Omron CX-Programmer project NewProject (CX-Programmer 7.23)

# PLC NewPLC1: CP1L L

## Program NewProgram1 (cyclic task 0)
; This program measures the amount of material that goes past a sensor using an encoder. / When the sensor is on we count the pulses from the High Speed Counter. / The E6B2-CWZ6C Encoder has 1000 pulses per revolution. / Because it is differential (A,B&Z Phases) we actually get 4000 pulses per revolution. / 1 revolution of the encoder equates to 1 foot of material. / Therefore the length of material in inches = pulses * 12 / 4000.
Local symbols
Gate_HSC_0 A531.08 BOOL
HSC0_PV A270 DINT
HSC0_PV_Inches D110 DINT
HSC0_PV_Storage D100 DINT
HSC0_PV_times_12 D105 DINT
HSC0_Reset A531.00 BOOL
Part_Present_Sensor 0.07 BOOL

### Section Section1
; High Speed Counter 0 (HSC0)

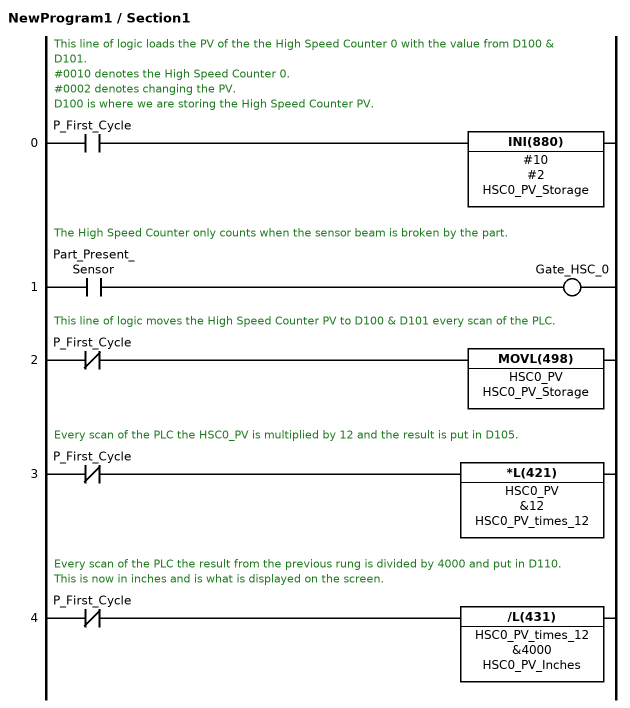
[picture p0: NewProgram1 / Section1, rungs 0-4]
; rung 0: This line of logic loads the PV of the the High Speed Counter 0 with the value from D100 & D101. / #0010 denotes the High Speed Counter 0. / #0002 denotes changing the PV. / D100 is where we are storing the High Speed Counter PV.
LD P_First_Cycle
INI(880) #10 #2 HSC0_PV_Storage
; rung 1: The High Speed Counter only counts when the sensor beam is broken by the part.
LD Part_Present_Sensor
OUT Gate_HSC_0
; rung 2: This line of logic moves the High Speed Counter PV to D100 & D101 every scan of the PLC.
LDNOT P_First_Cycle
MOVL(498) HSC0_PV HSC0_PV_Storage
; rung 3: Every scan of the PLC the HSC0_PV is multiplied by 12 and the result is put in D105.
LDNOT P_First_Cycle
*L(421) HSC0_PV &12 HSC0_PV_times_12
; rung 4: Every scan of the PLC the result from the previous rung is divided by 4000 and put in D110. / This is now in inches and is what is displayed on the screen.
LDNOT P_First_Cycle
/L(431) HSC0_PV_times_12 &4000 HSC0_PV_Inches

### Section END
; rung 0
END(001)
